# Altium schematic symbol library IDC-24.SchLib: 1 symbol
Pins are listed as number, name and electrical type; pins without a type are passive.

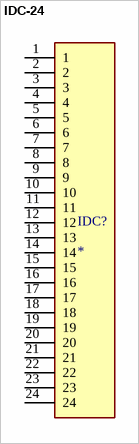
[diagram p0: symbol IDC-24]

## IDC-24
designator IDC?
IDC LOW PRO HDR 24P VERT BLUE; MF: TE Connectivity; MP: 2-1761603-8
footprint IDC-24
pins: 1, 2, 3, 4, 5, 6, 7, 8, 9, 10, 11, 12, 13, 14, 15, 16, 17, 18, 19, 20, 21, 22, 23, 24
